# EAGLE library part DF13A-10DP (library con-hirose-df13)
DF13-10DP Double row, 1.25mm Pitch Miniature Crimping Connector.
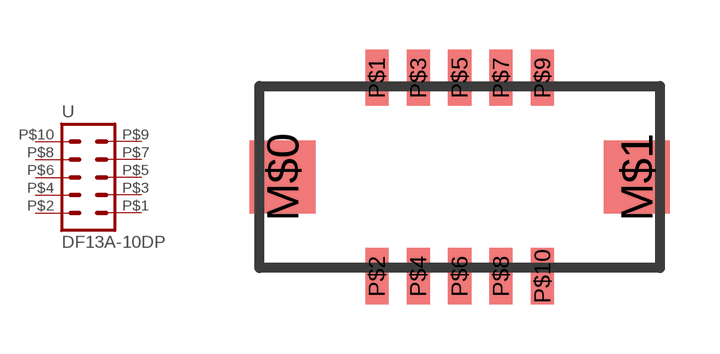
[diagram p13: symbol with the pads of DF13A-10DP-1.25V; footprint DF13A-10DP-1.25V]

Designator prefix -

## DF13A-10DP10DP-1.25V  [DF13A-10DP-1.25V]
P$1  1  pas
P$2  2  pas
P$3  3  pas
P$4  4  pas
P$5  5  pas
P$6  6  pas
P$7  7  pas
P$8  8  pas
P$9  9  pas
P$10  10  pas

## Footprint DF13A-10DP-1.25V (pad centres in mm)
Double Row Straight Pin Header (SMT)
smd 2 x 2.2: M$0 -5.35,0; M$1 5.35,0
smd 0.7 x 1.7: P$1 -2.5,3; P$2 -2.5,-3; P$3 -1.25,3; P$4 -1.25,-3; P$5 0,3; P$6 0,-3; P$7 1.25,3; P$8 1.25,-3; P$9 2.5,3; P$10 2.5,-3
